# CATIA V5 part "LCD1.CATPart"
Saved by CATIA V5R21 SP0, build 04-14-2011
Part number: LCD
Bounding box of the stored display mesh (mm): x -92.8 to 92.8, y -50 to 50, z 0 to 2.8
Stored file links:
  C:\Users\Pouria\Desktop\Box\Assembled\LCD1.CATPart
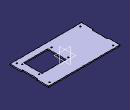
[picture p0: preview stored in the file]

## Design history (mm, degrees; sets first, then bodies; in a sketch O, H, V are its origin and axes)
Body1 (main body)
  Sketch1 on xy-plane, origin (0, 0, 0), H (1, 0, 0), V (0, 1, 0)
    line L1 (92.8, 50) -> (92.8, 20)
    line L2 (92.8, -50) -> (-92.8, -50)
    line L3 (-92.8, -50) -> (-92.8, -20)
    line L4 (-92.8, 50) -> (92.8, 50)
    point P1 (92.8, 50)
    point P2 (92.8, -50)
    line L5 (9.8, 13) -> (72.8, 13)
    line L6 (72.8, 13) -> (72.8, -35)
    line L7 (72.8, -35) -> (9.8, -35)
    line L8 (9.8, -35) -> (9.8, 13)
    line L9 (92.8, 20) -> (90, 20)
    line L10 (90, 20) -> (90, -20)
    line L11 (90, -20) -> (92.8, -20)
    point P12 (92.8, -20)
    point P13 (-92.8, 20)
    line L12 (-92.8, 20) -> (-90, 20)
    line L13 (-90, 20) -> (-90, -20)
    line L14 (-90, -20) -> (-92.8, -20)
    line L15 (92.8, -20) -> (92.8, -50)
    line L16 (-92.8, 20) -> (-92.8, 50)
    circle A1 centre (82.5, -42.5) radius 1.5
    point P17 (82.5, -42.5)
    circle A2 centre (82.5, 42.5) radius 1.5
    point P18 (82.5, 42.5)
    circle A3 centre (-82.5, 42.5) radius 1.5
    point P19 (-82.5, 42.5)
    circle A4 centre (-82.5, -42.5) radius 1.5
    point P20 (-82.5, -42.5)
    length L4 = 185.6
    length L5 = 63
    length L6 = 48
    distance L2 L7 = 15
    length L9 = 2.8
    length L13 = 40
    distance P1 P2 = 100
    distance L1 L6 = 20
    distance P17 L2 = 7.5
    distance P17 L10 = 7.5
    distance P20 L13 = 7.5
    distance P20 L2 = 7.5
    distance P19 L4 = 7.5
    distance P19 L13 = 7.5
    distance P18 L4 = 7.5
    distance P18 L10 = 7.5
    radius A2 = 1.5
    radius A3 = 1.5
    radius A4 = 1.5
    radius A1 = 1.5
    vertical: L1 V, L3 V, L6 V, L8 V, L10 V, L13 V, L15 V, L16 V
    horizontal: L2 H, L4 H, L5 H, L7 H, L9 H, L11 H, L12 H, L14 H
    equidistance: L1 L3 O, L2 L4 O
    coincidence: P12 L1, P13 L3, L9 L12, L11 L14, L1 L15, L3 L16
    symmetry: L12 L14 H, L11 L9 H, L10 L13 V
  Pad1: profile Sketch1, direction (0, 0, 1), length 2.8
  Sketch2 on end face of Pad1, origin (0, 0, 2.8), H (1, 0, 0), V (0, 1, 0)
    circle A1 centre (77.9, 10.95) radius 1.6
    point P1 (77.9, 10.95)
    circle A2 centre (77.9, -32.95) radius 1.6
    point P2 (77.9, -32.95)
    circle A3 centre (2, -32.95) radius 1.6
    point P3 (2, -32.95)
    circle A4 centre (2, 10.95) radius 1.6
    point P4 (2, 10.95)
    radius A1 = 1.6
    radius A2 = 1.6
    radius A3 = 1.6
    radius A4 = 1.6
    distance P4 V = 2
    distance P4 H = 10.95
    distance P3 V = 2
    distance P3 H = 32.95
    distance P1 V = 77.9
    distance P1 H = 10.95
    distance P2 V = 77.9
    distance P2 H = 32.95
  Pocket1: profile Sketch2, direction (0, 0, -1), through (limit type 3)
